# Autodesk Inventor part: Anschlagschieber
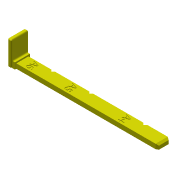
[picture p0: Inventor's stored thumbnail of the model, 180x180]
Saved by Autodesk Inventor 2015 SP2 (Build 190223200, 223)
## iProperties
Created: 2017-07
Material: ABS-gelb
Document SubType Name: Modeling
Designer: UR
Density: 1.06 g/cm^3
Appearance: Glatt - weiß
Part Number: Anschlagschieber
Author: UR
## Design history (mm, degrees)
sketch "Skizze1"
  geometry: L1 (-57, 4.9)-(57, 4.9); L2 (57, 4.9)-(57, -4.9); L3 (57, -4.9)-(-57, -4.9); L4 (-57, -4.9)-(-57, 4.9); L5 (0, -6.86)-(0, 6.86) reference; L6 (-79.8, 0)-(79.8, 0) reference; 1 further point
  constraints: 8 end point, 2 parallel, 1 horizontal, 1 perpendicular, 2 other
  dimensions: "d0" = 114 distance of L1.start L1.end; "d1" = 9.8 distance of L3.end L1.start
extrude "Schieberstange" new body sketch "Skizze1" distance "d2" = 3.8; taper "d3" = 0 deg
node "Schieberstange Mittelebene"
sketch "Skizze2"
  geometry: L1 (5, 10.9)-(0, 10.9); L2 (0, 10.9)-(0, -1.1); L3 (0, -1.1)-(5, -1.1); L4 (5, -1.1)-(5, 10.9); L5 (0, 0)-(0, 9.8) reference; L6 (0, 0)-(0, 9.8) reference; L7 (0, 0)-(3.8, 0) reference; L8 (3.8, 9.8)-(3.8, 0) reference; L9 (0, 9.8)-(3.8, 9.8) reference; L10 (0, 4.9)-(8.183, 4.9); 1 further point
  constraints: 10 end point, 2 horizontal, 2 midpoint, 2 parallel, 1 perpendicular
  dimensions: "d53" = 5 distance between parallel lines of L2 L4; "d54" = 12 distance between parallel lines of L3 L1
extrude "Anschlag" join sketch "Skizze2" distance "d6" = 2; taper "d7" = 0 deg
sketch "Skizze3"
  geometry: L1 (19, 11.9)-(1, 11.9); L2 (0, 10.9)-(0, -1.1); L3 (1, -2.1)-(19, -2.1); L4 (20, -1.1)-(20, 10.9); L5 (5, 10.9)-(0, 10.9) reference; L6 (0, 10.9)-(0, -1.1) reference; L7 (0, -1.1)-(5, -1.1) reference; L8 (5, -1.1)-(5, 10.9) reference; A1 r 1 centre (1, 10.9) between (1, 11.9) and (0, 10.9); A2 r 1 centre (1, -1.1) between (0, -1.1) and (1, -2.1); A3 r 1 centre (19, -1.1) between (19, -2.1) and (20, -1.1); A4 r 1 centre (19, 10.9) between (20, 10.9) and (19, 11.9); 1 further point
  constraints: 8 end point, 8 point on circle, 8 tangent, 4 centre point, 3 equal radius, 2 parallel, 1 collinear, 1 horizontal, 1 perpendicular
  dimensions: "d8" = 1 distance between parallel lines of L3 L7; "d9" = 1 distance between parallel lines of L5 L1; "d11" = 20 distance between parallel lines of L2 L4; "d12" = 1 radius of A1
extrude "Griff" join sketch "Skizze3" distance "d13" = 3; taper "d14" = 0 deg
node "Anschlagebene"
fillet "Rundung 1mm" dims "d15" = 0.9
sketch "Skizze Kerben und Taschen" dims "d39" = 10, "d46" = 10
  geometry: L1 (-59, -6)-(-59, -6.1) reference; L2 (-59, 6)-(-59, -6) reference; L3 (-59, 6.1)-(-59, 6) reference; L4 (-59, 6)-(-59, 6.1) reference; L5 (-59, -6)-(-59, 6) reference; L6 (-59, -6.1)-(-59, -6) reference; L7 (-111.5, -17.699)-(-111.5, 13.966); L8 (57, -4.9)-(57, 4.9) reference; L9 (-38.7, 4.9)-(-37.2, 3.4); L10 (-37.2, 3.4)-(-35.7, 4.9); L11 (-35.7, 4.9)-(-38.7, 4.9); L12 (57, 4.9)-(-57, 4.9) reference; L13 (-37.2, 3.4)-(-37.2, 4.9); L14 (-50.2, 3.5)-(-46.2, 3.5); L15 (-46.2, 3.5)-(-46.2, -3.5); L16 (-46.2, -3.5)-(-50.2, -3.5); L17 (-50.2, -3.5)-(-50.2, 3.5); L18 (90.3, 0)-(-142.8, 0) reference; L19 (-19.4, -3.5)-(-19.4, 3.5); L20 (-19.4, 3.5)-(-15.4, 3.5); L21 (-15.4, 3.5)-(-15.4, -3.5); L22 (-15.4, -3.5)-(-19.4, -3.5); L23 (-7.9, 4.9)-(-6.4, 3.4); L24 (-6.4, 3.4)-(-6.4, 4.9); L25 (-6.4, 3.4)-(-4.9, 4.9); L26 (-4.9, 4.9)-(-7.9, 4.9); L27 (24.2, -3.5)-(24.2, 3.5); L28 (28.2, -3.5)-(24.2, -3.5); L29 (28.2, 3.5)-(28.2, -3.5); L30 (24.2, 3.5)-(28.2, 3.5); L31 (35.7, 4.9)-(37.2, 3.4); L32 (37.2, 3.4)-(37.2, 4.9); L33 (37.2, 3.4)-(38.7, 4.9); L34 (38.7, 4.9)-(35.7, 4.9); L35 (-46.2, 4.9)-(-46.2, -4.9); L36 (-46.2, -4.9)-(-49.775, -4.9); L37 (-49.775, -4.9)-(-49.775, 4.9); L38 (-49.775, 4.9)-(-46.2, 4.9); L39 (-57, -4.9)-(57, -4.9) reference; L40 (-18.975, 4.9)-(-15.4, 4.9); L41 (-15.4, 4.9)-(-15.4, -4.9); L42 (-15.4, -4.9)-(-18.975, -4.9); L43 (-18.975, -4.9)-(-18.975, 4.9); L44 (24.625, 4.9)-(28.2, 4.9); L45 (28.2, 4.9)-(28.2, -4.9); L46 (28.2, -4.9)-(24.625, -4.9); L47 (24.625, -4.9)-(24.625, 4.9)
  constraints: 50 end point, 9 collinear, 3 horizontal, 3 parallel, 2 perpendicular, 1 midpoint, 1 vertical, 39 other
  dimensions: "d16" = 52.5 distance from line of L7 L1.end; "d17" = 3 distance of L10.end L9.start; "d18" = 74.3 distance between parallel lines of L13 L7; "d21" = 7 distance between parallel lines of L16 L14; "d22" = 4 distance between parallel lines of L15 L17; "d23" = 9 distance from line of L15 L9.end; "d36" = 30.8 distance of L14.start L19.end; "d43" = 43.6 distance of L19.start L27.start; "d48" = 105.1 distance between parallel lines of L24 L7 (derived); "d49" = 148.7 distance between parallel lines of L32 L7 (derived)
  node "Projizierte Kontur3"
extrude "Einrastkerbe" cut sketch "Skizze Kerben und Taschen" stored distance "d19" = 10; taper "d20" = 0 deg
extrude "Taschen für Markierung" cut sketch "Skizze Kerben und Taschen" distance "d24" = 2; taper "d25" = 0 deg
extrude "Beschriftung" cut sketch "Skizze Kerben und Taschen" distance "d51" = 0.5; taper "d52" = 0 deg
chamfer "Einfädelfase 1x60°" distance "d55" = 1; stored, may be unused: second distance "d56" = 2, angle "d57" = 60 deg
node "Rastkerbe A6"
node "Rastkerbe A5"
node "Rastkerbe A4"
node "Volumenkörper1"
node "Projizierte Kontur1"
node "Projizierte Kontur2"
other parameters: "d50" = 0, "d58" = 0, "d59" = 0
